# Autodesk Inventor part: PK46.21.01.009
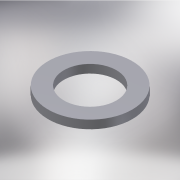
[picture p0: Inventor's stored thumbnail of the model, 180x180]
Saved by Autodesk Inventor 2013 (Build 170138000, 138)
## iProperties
Created: 2005-04
Part Number: PK46.21.01.009
Material: Steel, Mild
Document SubType Name: Modeling
Designer: salex
Manufacturer: Standard
Standards Organization: Custom
Density: 7.86 g/cm^3
Author: salex
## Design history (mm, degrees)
sketch "Эскиз1"
  geometry: C1 r 62.5 at (0, 0); C2 r 100 at (0, 0)
  constraints: 2 centre point, 1 coincident, 1 other
  dimensions: "d0" = 200 diameter of C2; "d1" = 125 diameter of C1
extrude "Выдавливание1" new body sketch "Эскиз1" distance "d2" = 20; taper "d3" = 0 deg
body "Solid1"
